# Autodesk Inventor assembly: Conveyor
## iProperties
Created: 2007-05
Part Number: Conveyor
Document SubType Name: Assembly
Designer: kurs1
Manufacturer: Standard
Standards Organization: Custom
Author: kurs1
